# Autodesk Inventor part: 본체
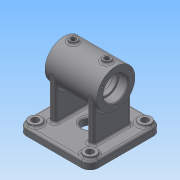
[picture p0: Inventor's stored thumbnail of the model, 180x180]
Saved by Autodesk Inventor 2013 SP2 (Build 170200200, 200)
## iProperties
Created: 2025-10
Part Number: 본체
Material: Generic
Document SubType Name: Modeling
Designer: a
Density: 1 g/cm^3
Author: a
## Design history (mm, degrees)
sketch "스케치1"
  geometry: L1 (47, 10)-(-47, 10); L2 (-47, 10)-(-47, 0); L3 (-47, 0)-(47, 0); L4 (47, 0)-(47, 10); 2 further points
  constraints: 8 end point, 2 midpoint, 2 parallel, 1 horizontal, 1 perpendicular, 1 vertical alignment
  dimensions: "d0" = 94 distance of L1.start L1.end; "d2" = 10 distance of L3.end L1.start
extrude "돌출1" new body sketch "스케치1" stored distance "d3" = 94; taper "d4" = 0 deg
sketch "스케치2"
  geometry: L1 (10, -47)-(0, -47) reference; L2 (0, -47)-(0, 47) reference; L3 (0, 47)-(10, 47) reference; L4 (10, 47)-(10, -47) reference; C1 r 25 at (66, 0); 2 further points
  constraints: 1 centre point, 1 horizontal alignment, 1 midpoint
  dimensions: "d5" = 50 diameter of C1; "d7" = 66 distance from line of L2 C1.centre
extrude "돌출2" join sketch "스케치2" stored distance "d8" = 68; taper "d9" = 0 deg
sketch "스케치3"
  geometry: L1 (0, 94)-(94, 94) reference; L2 (94, 94)-(94, 0) reference; L3 (94, 0)-(0, 0) reference; L4 (0, 0)-(0, 94) reference; L5 (68, 72)-(76, 72); L6 (76, 72)-(76, 22); L7 (76, 22)-(68, 22); L8 (68, 22)-(68, 72); 2 further points
  constraints: 8 end point, 2 parallel, 1 horizontal, 1 horizontal alignment, 1 midpoint, 1 perpendicular
  dimensions: "d10" = 8 distance of L5.start L5.end; "d12" = 50 distance of L5.end L6.end; "d13" = 21 distance from line of L8 point (47, 47)
extrude "돌출3" join sketch "스케치3" distance "d14" = 56; taper "d15" = 0 deg
node "작업 평면2"
  node "작업 평면1"
sketch "스케치4"
  geometry: L1 (-34, 25)-(-34, -25) reference; C1 r 5 at (-22, 0); 1 further point
  constraints: 1 centre point, 1 horizontal alignment
  dimensions: "d17" = 12 distance from line of C1.centre L1; "d18" = 10 diameter of C1
extrude "돌출4" join sketch "스케치4" distance "d19" = 10; taper "d20" = 0 deg
node "작업 평면4"
  node "작업 평면3"
sketch "스케치5"
  geometry: C1 r 6 at (0, 0); 1 further point
  constraints: 1 centre point, 1 coincident
  dimensions: "d22" = 12 diameter of C1
extrude "돌출5" join sketch "스케치5" distance "d23" = 10; taper "d24" = 0 deg
sketch "스케치6"
  geometry: C1 r 8 at (11, 83); 2 further points
  constraints: 1 centre point, 1 coincident
  dimensions: "d25" = 36 horizontal distance of point (47, 47) point (11, 83); "d26" = 36 horizontal distance of point (47, 47) point (11, 83); "d27" = 16 diameter of C1
extrude "돌출6" join sketch "스케치6" distance "d28" = 3; taper "d29" = 0 deg
hole "구멍1" diameter "d32" = 9; stored, may be unused: countersink angle "d36" = 90 deg, drill point angle "d38" = 118 deg; dims "d30" = 10, "d31" = 10, "d33" = 6, "d34" = 4, "d35" = 2, "d37" = 20
fillet "모깎기1" dims "d39" = 11
sketch "스케치7"
  geometry: L1 (21, 10)-(21, 41) reference; L2 (21, 41)-(6, 41) reference; L3 (6, 41)-(6, 38) reference; L4 (6, 38)-(-6, 38) reference; L5 (-6, 38)-(-6, 41) reference; L6 (-6, 41)-(-21, 41) reference; L7 (-21, 41)-(-21, 10) reference; L8 (-21, 10)-(21, 10) reference; L9 (-34, 41)-(-34, 91) reference; L10 (-34, 91)-(-27, 91) reference; L11 (-27, 91)-(-27, 94) reference; L12 (-27, 94)-(-17, 94) reference; L13 (-17, 94)-(-17, 91) reference; L14 (-17, 91)-(17, 91) reference; L15 (17, 91)-(17, 94) reference; L16 (17, 94)-(27, 94) reference; L17 (27, 94)-(27, 91) reference; L18 (27, 91)-(34, 91) reference; L19 (34, 91)-(34, 41) reference; L20 (34, 41)-(29, 41) reference; L21 (29, 41)-(29, 10) reference; L22 (29, 10)-(47, 10) reference; L23 (47, 10)-(47, 0) reference; L24 (47, 0)-(-47, 0) reference; L25 (-47, 0)-(-47, 10) reference; L26 (-47, 10)-(-29, 10) reference; L27 (-29, 10)-(-29, 41) reference; L28 (-29, 41)-(-34, 41) reference; L29 (-34, 66)-(34, 66); L30 (-34, 66)-(-34, 82); L31 (-34, 82)-(-22.3, 82); L32 (-22, 81.7)-(-22, 79.5); L33 (-22, 79.5)-(-16.258, 79.5); L34 (-16.258, 79.5)-(-5.696, 85.598); L35 (-4.196, 86)-(0, 86); L36 (0, 86)-(0, 66); L37 (34, 66)-(34, 82); L38 (34, 41)-(34, 91); L39 (22, 81.7)-(22, 79.5); L40 (34, 82)-(22.3, 82); L41 (22, 79.5)-(16.258, 79.5); L42 (16.258, 79.5)-(5.696, 85.598); L43 (4.196, 86)-(0, 86); A1 r 0.3 centre (22.3, 81.7) between (22.3, 82) and (22, 81.7); A2 r 0.3 centre (-22.3, 81.7) between (-22, 81.7) and (-22.3, 82); A3 r 3 centre (-4.196, 83) between (-4.196, 86) and (-5.696, 85.598); A4 r 3 centre (4.196, 83) between (5.696, 85.598) and (4.196, 86); 5 further points
  constraints: 30 end point, 10 point on line, 8 point on circle, 8 tangent, 5 symmetric about line, 4 centre point, 3 midpoint, 2 equal radius, 2 parallel, 2 perpendicular, 1 vertical
  dimensions: "d40" = 5 distance of point (-5, 86) L35.end; "d42" = 12 distance of L30.end point (-22, 82); "d43" = 30 deg angle of L29 L34; "d44" = 13.5 distance between parallel lines of L29 L33; "d45" = 16 distance between parallel lines of L31 L29; "d46" = 20 distance between parallel lines of L29 L35; "d48" = 0.3 radius of A1; "d49" = 3 radius of A3
revolve "회전1" sketch "스케치7" stored, may be unused: angle "d47" = 90 deg
hole "구멍2" diameter "d52" = 20; stored, may be unused: countersink angle "d56" = 90 deg, drill point angle "d58" = 118 deg; dims "d50" = 10, "d51" = 10, "d53" = 6, "d54" = 4, "d55" = 2, "d57" = 20
hole "구멍3" diameter "d61" = 5.188; stored, may be unused: countersink angle "d65" = 90 deg, drill point angle "d67" = 118 deg; dims "d59" = 10, "d60" = 10, "d62" = 6, "d63" = 6.6, "d64" = 2, "d66" = 20
hole "구멍4" diameter "d70" = 5.188; stored, may be unused: countersink angle "d74" = 90 deg, drill point angle "d76" = 118 deg; dims "d68" = 10, "d69" = 10, "d71" = 6, "d72" = 6.6, "d73" = 2, "d75" = 20
sketch "스케치8" dims "d77" = 41
  geometry: C1 r 16 at (0, 0) reference; C2 r 25 at (0, 0) reference; 5 further points
  constraints: 2 vertical alignment, 1 coincident, 6 other
  dimensions: "d80" = 360 deg dimension on C1.centre point (0, -20.5) (derived)
hole "구멍5" sketch "스케치8" at (0, -20.5), (17.754, 10.25), (-17.754, 10.25) diameter "d82" = 3.242; stored, may be unused: countersink angle "d86" = 90 deg, drill point angle "d88" = 118 deg; dims "d83" = 8, "d84" = 6.6, "d85" = 2, "d87" = 10
fillet "모깎기2" dims "d95" = 3
chamfer "모따기1" distance "d96" = 1; stored, may be unused: second distance "d97" = 2, angle "d98" = 45 deg
fillet "모깎기3" dims "d99" = 3
fillet "모깎기4" dims "d100" = 3
fillet "모깎기5" dims "d101" = 3
node "작업 평면6"
sketch "스케치11"
  geometry: L1 (-57.276, 67)-(57.276, 67); L2 (57.276, 67)-(57.276, 65); L3 (57.276, 65)-(-57.276, 65); L4 (-57.276, 65)-(-57.276, 67); L5 (-36, 0)-(36, 0) reference; 3 further points
  constraints: 2 midpoint, 1 vertical alignment, 2 other
  dimensions: "d108" = 65 distance between parallel lines of L3 L5; "d109" = 2 distance of L1.end L2.end
feature "엠보싱2" sketch "스케치11" dims "d0" = 94, "d2" = 10, "d10" = 8, "d12" = 50, "d13" = 21, "d110" = 0.5, "d111" = 0
node "솔리드1"
mirror "대칭1"
mirror "대칭2"
mirror "대칭3"
mirror "대칭4"
pattern_linear "직사각형 패턴1" dims "d91" = 72, "d94" = 72
node "절단 모서리 투영1"
node "절단 모서리 투영2"
node "절단 모서리 투영3"
other parameters: "d16" = 3, "d21" = -3, "d107" = 75.75
